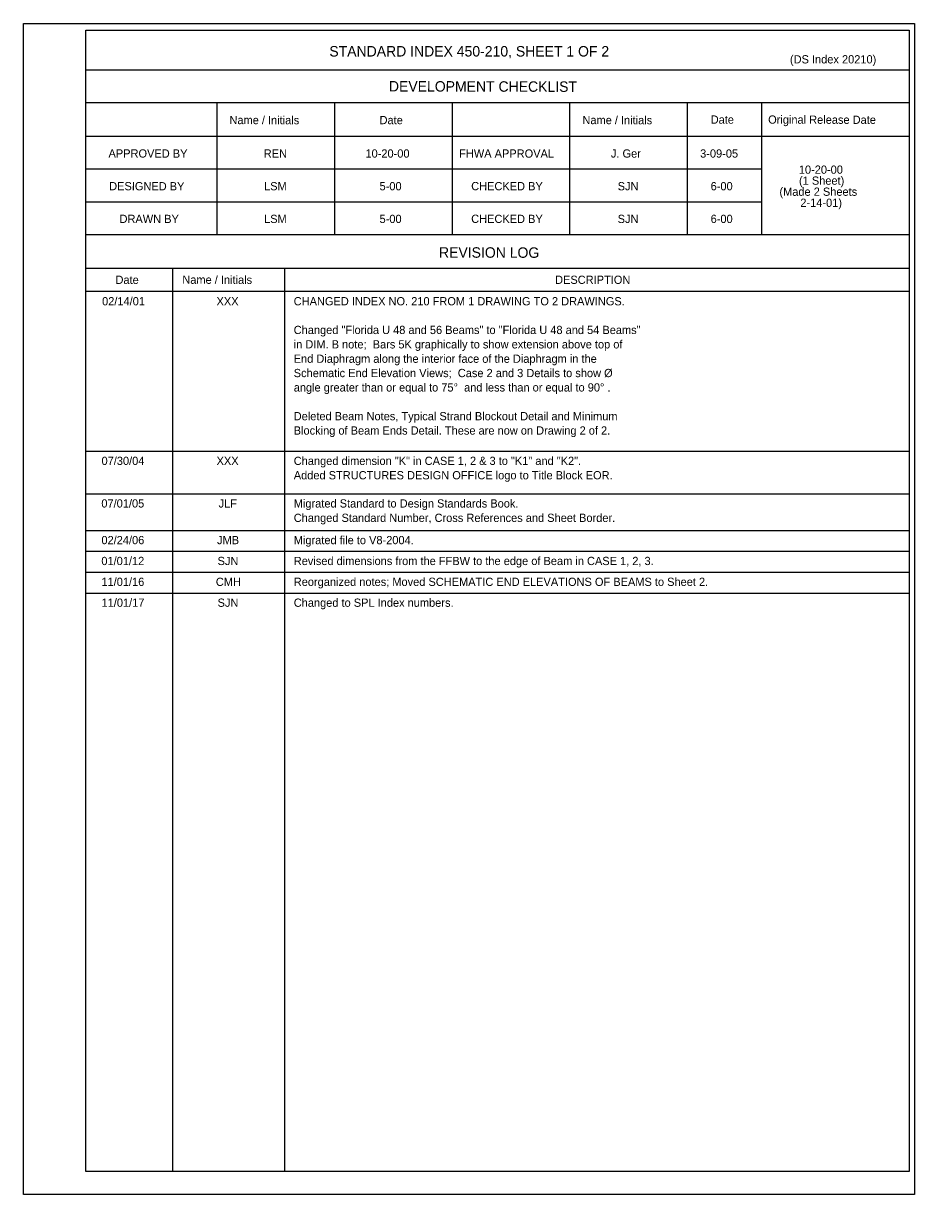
# Model space of a CAD drawing. Extents: x 120790.7 to 120844.8, y 120612.1 to 120653.6.
# Drawn here: x 120828.42 to 120844.78, y 120628.82 to 120650.32 of the extents above; entities that cross this region are included whole.
import ezdxf

# ---------------------------------------------------------------- set-up
doc = ezdxf.new("R2010")
doc.units = 0
for name, color, linetype in [('Border', 7, 'Continuous'), ('Patterning', 7, 'Continuous'), ('PlotBorder_dp', 7, 'Continuous'), ('SheetLines_dp', 7, 'Continuous')]:
    doc.layers.add(name, color=color, linetype=linetype)

msp = doc.modelspace()

# ---------------------------------------------------------------- linework, layer by layer
at = {"layer": 'Border'}
for p, q in [((120844.682, 120649.463), (120829.572, 120649.463)), ((120844.682, 120648.863), (120829.572, 120648.863)), ((120831.972, 120648.863), (120831.972, 120646.442)), ((120834.132, 120648.863), (120834.132, 120646.442)), ((120836.292, 120648.863), (120836.292, 120646.442)), ((120838.452, 120648.863), (120838.452, 120646.442)), ((120840.612, 120648.863), (120840.612, 120646.442)), ((120841.973, 120648.863), (120841.973, 120646.442)), ((120844.682, 120648.242), (120829.572, 120648.242)), ((120841.973, 120647.642), (120829.572, 120647.642)), ((120841.973, 120647.042), (120829.572, 120647.042)), ((120844.682, 120646.442), (120829.572, 120646.442)), ((120844.682, 120645.821), (120829.572, 120645.821)), ((120831.162, 120645.821), (120831.162, 120629.242)), ((120833.219, 120645.821), (120833.219, 120629.242)), ((120844.682, 120645.399), (120829.572, 120645.399))]:
    msp.add_line(p, q, dxfattribs=at)
msp.add_lwpolyline([(120829.572, 120650.199), (120844.682, 120650.199), (120844.682, 120629.242), (120829.572, 120629.242)], close=True, dxfattribs=at)
at = {"layer": 'PlotBorder_dp'}
for p, q in [((120829.572, 120642.468), (120844.682, 120642.468)), ((120829.572, 120641.686), (120844.682, 120641.686)), ((120829.572, 120641.014), (120844.682, 120641.014)), ((120829.572, 120640.631), (120844.682, 120640.631)), ((120829.572, 120640.248), (120844.682, 120640.248)), ((120829.572, 120639.864), (120844.682, 120639.864))]:
    msp.add_line(p, q, dxfattribs=at)
at = {"layer": 'SheetLines_dp'}
msp.add_line((120828.424, 120628.821), (120828.424, 120628.821), dxfattribs=at)
msp.add_lwpolyline([(120828.424, 120650.321), (120844.784, 120650.321), (120844.784, 120628.821), (120828.424, 120628.821)], close=True, dxfattribs=at)

# ---------------------------------------------------------------- texts
at = {"layer": 'Patterning'}
for s, height, p in [('STANDARD INDEX 450-210, SHEET 1 OF 2', 0.192, (120834.04, 120649.713)), ('(DS Index 20210)', 0.1512, (120842.496, 120649.586)), ('REN', 0.1512, (120832.836, 120647.857)), ('10-20-00', 0.1512, (120834.703, 120647.857)), ('J. Ger', 0.1512, (120839.209, 120647.857)), ('3-09-05', 0.1512, (120840.847, 120647.857)), ('10-20-00', 0.1512, (120842.659, 120647.561)), ('(1 Sheet)', 0.1512, (120842.662, 120647.359)), ('LSM', 0.1512, (120832.842, 120647.257)), ('5-00', 0.1512, (120834.962, 120647.257)), ('SJN', 0.1512, (120839.333, 120647.257)), ('6-00', 0.1512, (120841.04, 120647.257)), ('(Made 2 Sheets', 0.1512, (120842.303, 120647.156)), ('2-14-01)', 0.1512, (120842.687, 120646.953)), ('LSM', 0.1512, (120832.842, 120646.657)), ('5-00', 0.1512, (120834.962, 120646.657)), ('SJN', 0.1512, (120839.333, 120646.657)), ('6-00', 0.1512, (120841.04, 120646.657)), ('DESCRIPTION', 0.1512, (120838.184, 120645.539)), ('02/14/01', 0.1512, (120829.868, 120645.145)), ('XXX', 0.1512, (120831.969, 120645.145)), ('CHANGED INDEX NO. 210 FROM 1 DRAWING TO 2 DRAWINGS.', 0.1512, (120833.386, 120645.145)), ('Changed "Florida U 48 and 56 Beams" to "Florida U 48 and 54 Beams" ', 0.1512, (120833.386, 120644.618)), ('in DIM. B note;  Bars 5K graphically to show extension above top of ', 0.1512, (120833.386, 120644.354)), ('End Diaphragm along the interior face of the Diaphragm in the ', 0.1512, (120833.386, 120644.09)), ('Schematic End Elevation Views;  Case 2 and 3 Details to show Ø', 0.1512, (120833.386, 120643.827)), ('angle greater than or equal to 75°  and less than or equal to 90° .', 0.1512, (120833.386, 120643.563)), ('Deleted Beam Notes, Typical Strand Blockout Detail and Minimum', 0.1512, (120833.386, 120643.035)), ('Blocking of Beam Ends Detail. These are now on Drawing 2 of 2.', 0.1512, (120833.386, 120642.772)), ('07/30/04', 0.1512, (120829.858, 120642.215)), ('XXX', 0.1512, (120831.97, 120642.215)), ('Changed dimension "K" in CASE 1, 2 & 3 to "K1" and "K2".', 0.1512, (120833.387, 120642.215)), ('Added STRUCTURES DESIGN OFFICE logo to Title Block EOR.', 0.1512, (120833.387, 120641.951)), ('07/01/05', 0.1512, (120829.855, 120641.433)), ('JLF', 0.1512, (120832.007, 120641.433)), ('Migrated Standard to Design Standards Book.', 0.1512, (120833.387, 120641.433)), ('Changed Standard Number, Cross References and Sheet Border.', 0.1512, (120833.387, 120641.169)), ('02/24/06', 0.1512, (120829.856, 120640.76)), ('JMB', 0.1512, (120831.979, 120640.76)), ('Migrated file to V8-2004.', 0.1512, (120833.387, 120640.76)), ('01/01/12', 0.1512, (120829.855, 120640.377)), ('SJN', 0.1512, (120831.988, 120640.377)), ('Revised dimensions from the FFBW to the edge of Beam in CASE 1, 2, 3.', 0.1512, (120833.387, 120640.377)), ('11/01/16', 0.1512, (120829.856, 120639.994)), ('CMH', 0.1512, (120831.956, 120639.994)), ('Reorganized notes; Moved SCHEMATIC END ELEVATIONS OF BEAMS to Sheet 2.', 0.1512, (120833.387, 120639.994)), ('11/01/17', 0.1512, (120829.858, 120639.611)), ('SJN', 0.1512, (120831.988, 120639.611)), ('Changed to SPL Index numbers.', 0.1512, (120833.387, 120639.611))]:
    msp.add_text(s, height=height, dxfattribs=at).set_placement(p)
for s, height, p in [('DEVELOPMENT CHECKLIST', 0.192, (120835.134, 120649.071)), ('Name / Initials', 0.1512, (120832.206, 120648.472)), ('Date', 0.1512, (120834.962, 120648.471)), ('Name / Initials', 0.1512, (120838.686, 120648.472)), ('Date', 0.1512, (120841.041, 120648.48)), ('Original Release Date', 0.1512, (120842.096, 120648.48)), ('APPROVED BY', 0.1512, (120829.986, 120647.859)), ('FHWA APPROVAL', 0.1512, (120836.423, 120647.859)), ('DESIGNED BY', 0.1512, (120829.998, 120647.258)), ('CHECKED BY', 0.1512, (120836.644, 120647.259)), ('DRAWN BY', 0.1512, (120830.188, 120646.658)), ('CHECKED BY', 0.1512, (120836.644, 120646.659)), ('REVISION LOG', 0.192, (120836.053, 120646.021)), ('Date', 0.1512, (120830.114, 120645.539)), ('Name / Initials', 0.1512, (120831.341, 120645.541))]:
    msp.add_text(s, height=height, rotation=359.8756, dxfattribs=at).set_placement(p)

doc.saveas('drawing.dxf')
